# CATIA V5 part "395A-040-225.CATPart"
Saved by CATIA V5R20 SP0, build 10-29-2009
Part number: 395A-040-225
Source: Unknown
Property "ARTICLENO": "395A-040-225"
Property "B": "10"
Property "BOMINFO": "395A-040-225"
Property "C": "13.000"
Property "CODE": "395A-040-225"
Property "D": "40.000"
Property "D1": "50.000"
Property "D2": "4x12"
Property "D3": "16"
Property "D5": "30"
Property "D6": "28.000"
Property "H": "6.000"
Property "L": "225.000"
Property "L1": "10.000"
Property "L2": "188.000"
Property "L3": "13.000"
Property "L4": "13"
Property "LINA": "395A-040-225"
Property "M": "12.000"
Property "M1": "14.000"
Property "M2": "13.000"
Property "MAXLOAD": "5000 Kg"
Property "MDW": "10000 Kg"
Property "NB": "395A-040-225"
Property "NBSYN": "$CODE."
Property "NN": "395A"
Property "NT": "Pin"
Property "P": "6"
Property "S": "13.000"
Property "SUPPLIER": "CF"
Bounding box of the stored display mesh (mm): x 0 to 225, y -26 to 25, z -25 to 25
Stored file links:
  C:\Users\Utente\Desktop\3D files 395A\395A-040-225.CATPart
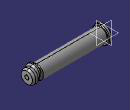
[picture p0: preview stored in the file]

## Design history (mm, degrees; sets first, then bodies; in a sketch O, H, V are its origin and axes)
Body1 "Geometry.1" (main body)
  Solid1 "395A-040-225.catpart": solid without history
